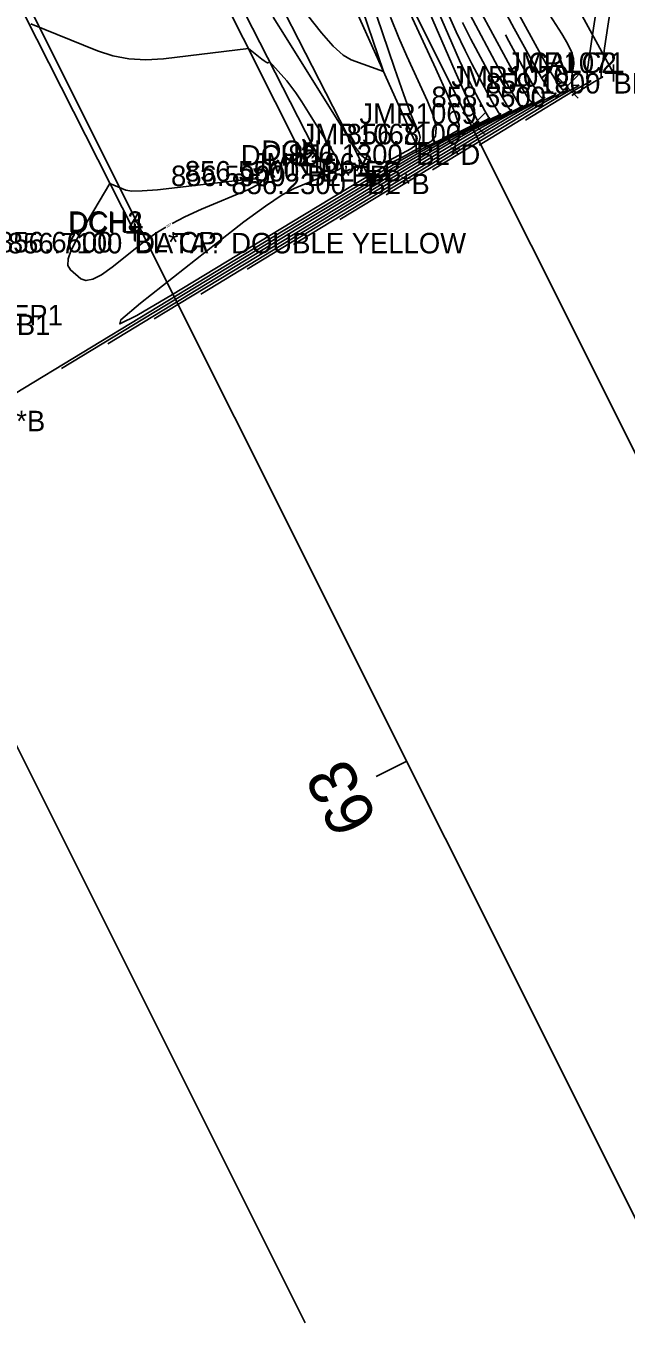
# Model space of a CAD drawing. Extents: x 1654928 to 1810050, y 486881 to 626330.
# Drawn here: x 1801517.2 to 1801552.3, y 489574.4 to 489650.4 of the extents above; entities that cross this region are included whole.
import ezdxf

# ---------------------------------------------------------------- set-up
doc = ezdxf.new("R2010")
doc.units = 0
for name, color, linetype in [('DR_X_Ditch', 7, 'Continuous'), ('DT_X_Contour_Major', 7, 'Continuous'), ('DT_X_Contour_Minor', 7, 'Continuous'), ('PV_X_EOP', 7, 'Continuous'), ('PV_X_Shoulder', 7, 'Continuous'), ('RD_X_Fence', 7, 'Continuous'), ('RW_X_Esmt_SH', 7, 'Continuous'), ('SV_X_Break_Lines', 7, 'Continuous'), ('SV_X_Center_of_Pavt', 7, 'Continuous'), ('SV_X_CL_Survey_20', 7, 'Continuous'), ('SV_X_Random_Point', 7, 'Continuous'), ('SV_X_Shot_Marker', 7, 'Continuous'), ('SV_X_Text_Comment', 7, 'Continuous'), ('SV_X_Text_Elevation', 7, 'Continuous'), ('SV_X_Text_Name', 7, 'Continuous')]:
    doc.layers.add(name, color=color, linetype=linetype)

msp = doc.modelspace()

# ---------------------------------------------------------------- linework, layer by layer
at = {"layer": 'DR_X_Ditch'}
msp.add_lwpolyline([(1801540.062, 489643.432), (1801532.556, 489660.144), (1801517.868, 489690.883), (1801504.345, 489723.544), (1801491.469, 489750.565), (1801478.102, 489779.895), (1801464.666, 489805.356), (1801460.448, 489815.434)], dxfattribs=at)
at = {"layer": 'DT_X_Contour_Major'}
for points in [[(1801535.072, 489656.744), (1801538.149, 489647.692), (1801536.257, 489648.374), (1801535.794, 489648.647), (1801535.216, 489649.174), (1801534.523, 489649.954), (1801533.714, 489650.989)], [(1801551.876, 489654.299), (1801551.274, 489650.342), (1801551.079, 489649.044), (1801550.948, 489648.117), (1801550.881, 489647.561), (1801550.877, 489647.377), (1801550.951, 489647.382), (1801550.97, 489647.38), (1801550.971, 489647.373), (1801550.955, 489647.361), (1801550.921, 489647.342), (1801550.807, 489647.285), (1801550.741, 489647.249), (1801550.464, 489647.085), (1801549.16, 489646.295)], [(1801541.108, 489651.737), (1801541.946, 489649.816), (1801542.602, 489648.337), (1801543.075, 489647.302), (1801543.366, 489646.708), (1801543.897, 489645.717), (1801544.073, 489645.392), (1801544.204, 489645.16), (1801544.288, 489645.021), (1801544.326, 489644.975), (1801544.367, 489644.978), (1801544.316, 489644.946), (1801544.132, 489644.85), (1801543.815, 489644.688), (1801543.365, 489644.462), (1801541.988, 489643.772), (1801541.182, 489643.33), (1801539.795, 489642.523), (1801537.828, 489641.35), (1801535.281, 489639.811), (1801522.039, 489631.776)], [(1801545.279, 489649.831), (1801545.476, 489649.462), (1801546.26, 489648.016), (1801546.84, 489646.984), (1801547.214, 489646.366), (1801547.385, 489646.163), (1801547.566, 489646.174), (1801547.59, 489646.16), (1801547.528, 489646.11), (1801547.379, 489646.024), (1801547.143, 489645.902), (1801546.398, 489645.528), (1801545.961, 489645.289), (1801545.211, 489644.852), (1801544.146, 489644.217), (1801542.767, 489643.384), (1801535.599, 489639.036)]]:
    msp.add_lwpolyline(points, dxfattribs=at)
at = {"layer": 'DT_X_Contour_Minor'}
for points in [[(1801538.562, 489656.405), (1801542.345, 489647.695), (1801542.899, 489646.428), (1801543.256, 489645.621), (1801543.416, 489645.276), (1801543.636, 489644.867), (1801543.676, 489644.795), (1801543.702, 489644.752), (1801543.714, 489644.738), (1801543.727, 489644.739), (1801543.452, 489644.598), (1801541.106, 489643.421), (1801540.226, 489642.938), (1801538.712, 489642.057), (1801536.565, 489640.776), (1801533.784, 489639.096), (1801519.327, 489630.325)], [(1801535.974, 489656.196), (1801538.094, 489649.959), (1801538.804, 489647.881), (1801539.345, 489646.323), (1801539.717, 489645.286), (1801539.919, 489644.77), (1801540.234, 489644.088), (1801540.292, 489643.839), (1801540.229, 489643.604), (1801540.047, 489643.382), (1801539.745, 489643.174), (1801538.78, 489642.636), (1801538.443, 489642.467), (1801538.155, 489642.363), (1801537.917, 489642.324), (1801537.729, 489642.35), (1801537.294, 489642.507), (1801537.137, 489642.578), (1801536.993, 489642.671), (1801536.861, 489642.788), (1801536.742, 489642.928), (1801536.215, 489643.635), (1801532.458, 489649.665), (1801531.692, 489650.866)], [(1801543.063, 489655.305), (1801545.792, 489650.211), (1801546.698, 489648.541), (1801547.367, 489647.349), (1801547.8, 489646.635), (1801547.996, 489646.401), (1801548.206, 489646.413), (1801548.245, 489646.403), (1801548.207, 489646.362), (1801548.092, 489646.291), (1801547.898, 489646.19), (1801547.28, 489645.88), (1801546.917, 489645.681), (1801546.294, 489645.318), (1801545.409, 489644.791), (1801544.264, 489644.099), (1801538.312, 489640.487)], [(1801550.919, 489653.449), (1801550.369, 489649.833), (1801550.195, 489648.647), (1801550.088, 489647.801), (1801550.047, 489647.294), (1801550.072, 489647.128), (1801550.228, 489647.137), (1801550.268, 489647.135), (1801550.271, 489647.12), (1801550.237, 489647.093), (1801550.165, 489647.054), (1801549.925, 489646.934), (1801549.785, 489646.857), (1801549.543, 489646.716), (1801549.2, 489646.512), (1801546.448, 489644.843)], [(1801539.107, 489652.413), (1801541.216, 489647.836), (1801541.894, 489646.326), (1801542.344, 489645.229), (1801542.566, 489644.544), (1801542.562, 489644.272), (1801542.245, 489644.096), (1801542.085, 489644.01), (1801541.842, 489643.884), (1801541.516, 489643.718), (1801541.107, 489643.511), (1801539.904, 489642.909), (1801539.09, 489642.456), (1801537.549, 489641.551), (1801535.281, 489640.193), (1801532.286, 489638.381), (1801516.615, 489628.873)], [(1801543.164, 489652.439), (1801545.161, 489648.713), (1801545.823, 489647.491), (1801546.312, 489646.619), (1801546.629, 489646.097), (1801546.773, 489645.926), (1801546.926, 489645.935), (1801546.935, 489645.917), (1801546.849, 489645.858), (1801546.666, 489645.757), (1801546.387, 489645.614), (1801545.516, 489645.177), (1801545.005, 489644.898), (1801544.128, 489644.386), (1801542.882, 489643.644), (1801541.27, 489642.67), (1801532.887, 489637.584)], [(1801541.774, 489651.416), (1801542.406, 489650.015), (1801542.92, 489648.924), (1801543.315, 489648.141), (1801544.213, 489646.466), (1801544.511, 489645.917), (1801544.731, 489645.525), (1801544.873, 489645.29), (1801544.938, 489645.213), (1801545.007, 489645.217), (1801544.971, 489645.189), (1801544.811, 489645.102), (1801544.528, 489644.956), (1801544.121, 489644.75), (1801542.87, 489644.123), (1801542.138, 489643.722), (1801540.878, 489642.989), (1801539.092, 489641.923), (1801536.778, 489640.526), (1801524.751, 489633.228)], [(1801543.215, 489651.006), (1801544.845, 489647.964), (1801545.386, 489646.966), (1801545.785, 489646.254), (1801546.044, 489645.828), (1801546.161, 489645.688), (1801546.286, 489645.696), (1801546.28, 489645.675), (1801546.169, 489645.606), (1801545.953, 489645.49), (1801545.632, 489645.326), (1801544.634, 489644.826), (1801544.05, 489644.506), (1801543.044, 489643.921), (1801541.619, 489643.07), (1801539.773, 489641.955), (1801530.175, 489636.132)], [(1801546.108, 489650.96), (1801547.135, 489649.065), (1801547.894, 489647.714), (1801548.385, 489646.904), (1801548.608, 489646.638), (1801548.845, 489646.653), (1801548.9, 489646.646), (1801548.887, 489646.614), (1801548.805, 489646.558), (1801548.654, 489646.478), (1801548.161, 489646.231), (1801547.873, 489646.073), (1801547.377, 489645.784), (1801546.673, 489645.364), (1801545.762, 489644.814), (1801541.024, 489641.939)], [(1801547.533, 489651.532), (1801548.58, 489649.9), (1801548.918, 489649.331), (1801549.148, 489648.847), (1801549.269, 489648.448), (1801549.282, 489648.134), (1801549.172, 489647.411), (1801549.147, 489647.174), (1801549.155, 489647.006), (1801549.195, 489646.908), (1801549.268, 489646.879), (1801549.506, 489646.893), (1801549.567, 489646.889), (1801549.571, 489646.867), (1801549.519, 489646.826), (1801549.41, 489646.766), (1801549.043, 489646.582), (1801548.829, 489646.465), (1801548.46, 489646.25), (1801547.937, 489645.938), (1801547.259, 489645.529), (1801543.736, 489643.391)], [(1801538.562, 489650.862), (1801539.048, 489649.652), (1801539.513, 489648.591), (1801540.725, 489645.962), (1801541.081, 489645.076), (1801541.24, 489644.39), (1801541.201, 489643.904), (1801540.966, 489643.618), (1801539.757, 489642.946), (1801539.471, 489642.791), (1801539.216, 489642.657), (1801538.993, 489642.542), (1801538.44, 489642.265), (1801537.932, 489641.976), (1801536.821, 489641.316), (1801535.108, 489640.284), (1801532.792, 489638.882), (1801525.814, 489634.648), (1801523.735, 489633.426), (1801522.732, 489632.934), (1801522.804, 489633.173), (1801523.951, 489634.143), (1801528.445, 489637.702), (1801529.989, 489638.9), (1801531.251, 489639.822), (1801532.232, 489640.47), (1801532.932, 489640.843), (1801534.421, 489641.47), (1801534.913, 489641.679), (1801535.274, 489641.835), (1801535.503, 489641.94), (1801535.601, 489641.991), (1801535.685, 489642.059), (1801535.66, 489642.167), (1801535.52, 489642.438), (1801535.267, 489642.874), (1801534.899, 489643.473), (1801533.767, 489645.29), (1801533.369, 489645.917), (1801533.024, 489646.434), (1801532.731, 489646.841), (1801532.491, 489647.139), (1801531.495, 489648.274), (1801531.408, 489648.193), (1801531.371, 489648.195), (1801531.296, 489648.233), (1801531.184, 489648.308), (1801531.035, 489648.419), (1801530.252, 489649.028), (1801525.295, 489648.437), (1801524.257, 489648.37), (1801523.267, 489648.424), (1801522.327, 489648.597), (1801521.434, 489648.891), (1801517.527, 489650.485)], [(1801542.764, 489650.546), (1801543.265, 489649.574), (1801544.529, 489647.215), (1801544.948, 489646.442), (1801545.258, 489645.89), (1801545.458, 489645.559), (1801545.549, 489645.451), (1801545.646, 489645.456), (1801545.626, 489645.432), (1801545.49, 489645.354), (1801545.24, 489645.223), (1801544.876, 489645.038), (1801543.752, 489644.474), (1801543.094, 489644.114), (1801541.961, 489643.455), (1801540.355, 489642.497), (1801538.275, 489641.24), (1801527.463, 489634.68)], [(1801525.426, 489638.593), (1801524.841, 489638.232), (1801524.116, 489637.704), (1801522.292, 489636.26), (1801521.665, 489635.81), (1801521.151, 489635.545), (1801520.75, 489635.464), (1801520.463, 489635.568), (1801519.847, 489636.091), (1801519.697, 489636.35), (1801519.708, 489636.734), (1801519.881, 489637.244), (1801520.216, 489637.879), (1801522.154, 489641.135), (1801523.089, 489640.754)], [(1801523.089, 489640.754), (1801523.428, 489640.702), (1801524.045, 489640.71), (1801524.941, 489640.777), (1801526.115, 489640.904), (1801529.616, 489641.321), (1801530.638, 489641.405), (1801531.078, 489641.343), (1801530.937, 489641.134), (1801530.214, 489640.78), (1801527.511, 489639.642), (1801526.539, 489639.201), (1801525.788, 489638.804)]]:
    msp.add_lwpolyline(points, dxfattribs=at)
at = {"layer": 'PV_X_EOP'}
msp.add_lwpolyline([(1801533.684, 489642.188), (1801522.484, 489664.508), (1801511.881, 489685.341), (1801500.299, 489708.684), (1801491.104, 489726.659), (1801480.832, 489747.383), (1801466.882, 489774.659), (1801456.506, 489795.715), (1801444.637, 489819.009), (1801433.258, 489841.444), (1801422.029, 489863.995), (1801410.905, 489885.928), (1801399.817, 489908.089), (1801388.576, 489930.656), (1801376.228, 489955.188), (1801366.008, 489975.62), (1801354.725, 489997.894)], dxfattribs=at)
at = {"layer": 'PV_X_Shoulder'}
msp.add_lwpolyline([(1801534.471, 489642.456), (1801522.963, 489664.954), (1801512.6, 489685.485), (1801500.973, 489709.112), (1801491.766, 489727.019), (1801481.526, 489747.768), (1801467.484, 489775.07), (1801457.116, 489796.092), (1801445.57, 489819.398), (1801434.029, 489841.927), (1801422.682, 489864.343), (1801411.885, 489886.25), (1801400.664, 489908.455), (1801366.703, 489976.232), (1801355.676, 489998.276)], dxfattribs=at)
at = {"layer": 'RD_X_Fence'}
msp.add_lwpolyline([(1801551.601, 489647.601), (1801542.924, 489663.468), (1801525.109, 489695.967), (1801509.688, 489725.543), (1801495.067, 489753.216), (1801479.522, 489782.185), (1801467.623, 489805.516), (1801461.848, 489815.569), (1801444.198, 489848.97), (1801434.479, 489868.8), (1801422.196, 489892.762), (1801414.797, 489907.008)], dxfattribs=at)
at = {"layer": 'RW_X_Esmt_SH'}
for p, q in [((1801569.151, 489592.806), (1801345.762, 490039.449)), ((1801533.563, 489574.54), (1801308.538, 490024.454))]:
    msp.add_line(p, q, dxfattribs=at)
at = {"layer": 'SV_X_Break_Lines'}
msp.add_lwpolyline([(1801537.196, 489641.719), (1801528.364, 489658.964), (1801513.29, 489687.828), (1801498.001, 489720.37), (1801485.256, 489748.381), (1801470.065, 489776.956), (1801457.973, 489802.299), (1801452.712, 489809.925), (1801448.007, 489818.919)], dxfattribs=at)
at = {"layer": 'SV_X_Center_of_Pavt'}
msp.add_lwpolyline([(1801523.585, 489638.313), (1801512.853, 489659.481), (1801502.374, 489680.412), (1801490.819, 489703.952), (1801481.428, 489721.68), (1801470.803, 489742.834), (1801457.335, 489769.613), (1801446.389, 489792.464), (1801435.307, 489813.792), (1801423.54, 489836.522), (1801412.234, 489859.298), (1801401.202, 489881.345), (1801390.005, 489903.67), (1801378.784, 489926.715), (1801366.669, 489950.371), (1801356.567, 489970.63), (1801345.517, 489992.708)], dxfattribs=at)
at = {"layer": 'SV_X_CL_Survey_20'}
for p, q in [((1802886.975, 486913.246), (1801128.538, 490429.055)), ((1802886.975, 486913.246), (1801128.538, 490429.055)), ((1801539.507, 489607.366), (1801537.718, 489606.471))]:
    msp.add_line(p, q, dxfattribs=at)
at = {"layer": 'SV_X_Random_Point'}
for p, q in [((1801548.206, 489646.137), (1801549.54, 489647.472)), ((1801548.206, 489647.472), (1801549.54, 489646.137)), ((1801542.772, 489643.964), (1801544.106, 489645.298)), ((1801542.772, 489645.298), (1801544.106, 489643.964))]:
    msp.add_line(p, q, dxfattribs=at)
at = {"layer": 'SV_X_Shot_Marker'}
for p, q in [((1801551.601, 489648.101), (1801551.601, 489647.101)), ((1801551.601, 489648.101), (1801551.601, 489647.101)), ((1801551.101, 489647.601), (1801552.101, 489647.601)), ((1801551.101, 489647.601), (1801552.101, 489647.601)), ((1801551.601, 489647.601), (1801551.601, 489647.601)), ((1801551.601, 489647.601), (1801551.601, 489647.601)), ((1801539.562, 489643.432), (1801540.562, 489643.432)), ((1801540.062, 489643.932), (1801540.062, 489642.932)), ((1801540.062, 489643.432), (1801540.062, 489643.432)), ((1801533.684, 489642.688), (1801533.684, 489641.688)), ((1801534.471, 489642.956), (1801534.471, 489641.956)), ((1801533.184, 489642.188), (1801534.184, 489642.188)), ((1801533.684, 489642.188), (1801533.684, 489642.188)), ((1801533.971, 489642.456), (1801534.971, 489642.456)), ((1801534.471, 489642.456), (1801534.471, 489642.456)), ((1801537.196, 489642.219), (1801537.196, 489641.219)), ((1801536.696, 489641.719), (1801537.696, 489641.719)), ((1801537.196, 489641.719), (1801537.196, 489641.719)), ((1801523.585, 489638.813), (1801523.585, 489637.813)), ((1801523.63, 489638.755), (1801523.63, 489637.755)), ((1801523.085, 489638.313), (1801524.085, 489638.313)), ((1801523.13, 489638.255), (1801524.13, 489638.255)), ((1801523.585, 489638.313), (1801523.585, 489638.313)), ((1801523.63, 489638.255), (1801523.63, 489638.255))]:
    msp.add_line(p, q, dxfattribs=at)

# ---------------------------------------------------------------- texts
at = {"layer": 'DT_X_Contour_Minor'}
msp.add_text('857', height=0.14, rotation=30.25168, dxfattribs=at).set_placement((1801525.502, 489638.562))
at = {"layer": 'SV_X_CL_Survey_20'}
msp.add_text('63', height=2.8, rotation=116.572, dxfattribs=at).set_placement((1801537.859, 489603.954))
at = {"layer": 'SV_X_Text_Comment'}
for s, p in [("BL*FEN FENDAT TYPE? WOOD HEIGHT? 4.5' OWNER? FARMER ELECTRIC", (1801551.601, 489646.401)), ('BL*D', (1801540.062, 489642.232)), ('BL*EP', (1801533.684, 489640.988)), ('BL*EB', (1801534.471, 489641.256)), ('BL*B', (1801537.196, 489640.519)), ('BL*CP', (1801523.585, 489637.113)), ('DATA? DOUBLE YELLOW', (1801523.63, 489637.055)), ('BL*EB1', (1801513.053, 489632.284)), ('BL*EP1', (1801513.785, 489632.843)), ('BL*B', (1801514.716, 489626.656))]:
    msp.add_text(s, height=1.2, dxfattribs=at).set_placement(p)
at = {"layer": 'SV_X_Text_Elevation'}
for s, p in [('859.1800', (1801544.137, 489646.401)), ('859.1800', (1801544.137, 489646.401)), ('858.5500', (1801540.955, 489645.605)), ('856.7100', (1801535.994, 489643.431)), ('856.1300', (1801532.579, 489642.232)), ('856.5900', (1801525.728, 489640.988)), ('856.5500', (1801526.534, 489641.256)), ('856.2300', (1801529.259, 489640.519)), ('856.6600', (1801515.61, 489637.113)), ('856.7100', (1801516.186, 489637.055))]:
    msp.add_text(s, height=1.2, dxfattribs=at).set_placement(p)
at = {"layer": 'SV_X_Text_Name'}
for s, p in [('JMR1071', (1801545.384, 489647.601)), ('CALC2', (1801546.612, 489647.601)), ('JMR1070', (1801542.118, 489646.805)), ('JMR1069', (1801536.741, 489644.631)), ('JMR1068', (1801533.363, 489643.432)), ('DCH2', (1801529.81, 489642.188)), ('DCH1', (1801531.021, 489642.456)), ('JMR1067', (1801530.507, 489641.719)), ('DCH3', (1801519.702, 489638.313)), ('DCH4', (1801519.757, 489638.255))]:
    msp.add_text(s, height=1.2, dxfattribs=at).set_placement(p)

doc.saveas('drawing.dxf')
